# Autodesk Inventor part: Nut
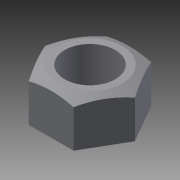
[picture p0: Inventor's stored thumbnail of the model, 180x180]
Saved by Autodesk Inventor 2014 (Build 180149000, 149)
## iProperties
Created: 2004-07
Part Number: Nut
Document SubType Name: Modeling
Designer: Autodesk, Inc.
Manufacturer: Standard
Standards Organization: Custom
Density: 1 g/cm^3
Mass: 3.54479 g
Surface Area: 21.3114 cm^2
Volume: 3.54479 cm^3
Material: Generic
Appearance: Default
Author: Autodesk, Inc.
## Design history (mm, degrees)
sketch "Sketch1"
  geometry: L1 (-13.279, 0)-(-6.64, 11.5); L2 (-6.64, 11.5)-(6.64, 11.5); L3 (6.64, 11.5)-(13.279, 0); L4 (13.279, 0)-(6.64, -11.5); L5 (6.64, -11.5)-(-6.64, -11.5); L6 (-6.64, -11.5)-(-13.279, 0); 2 further points
  constraints: 12 end point, 1 coincident, 11 other
  dimensions: "d0" = 23 distance between parallel lines of L2 L5
extrude "Extrusion1" new body sketch "Sketch1" distance "d1" = 13; taper "d2" = 0 deg
sketch "Sketch2"
  geometry: L1 (0, -2.8)-(0, 16.8) reference; L2 (13.6, 14)-(13.6, 11); L3 (13.6, 11)-(7.6, 14); L4 (7.6, 14)-(13.6, 14); L5 (13.279, 0)-(6.64, 0) reference; L6 (6.64, 0)-(-6.64, 0) reference; L7 (-6.64, 0)-(-13.279, 0) reference; L8 (-13.279, 0)-(-6.64, 0) reference; L9 (-6.64, 0)-(6.64, 0) reference; L10 (6.64, 0)-(13.279, 0) reference
  constraints: 6 end point, 1 parallel, 1 perpendicular
  dimensions: "d3" = 27.2 diameter of L2 L1; "d4" = 6 distance of L3.end L2.start; "d5" = 3 distance of L2.start L2.end; "d6" = 14 distance between parallel lines of L4 L5
revolve "Revolution1" sketch "Sketch2" stored, may be unused: angle "d7" = 90 deg
sketch "Sketch3"
  geometry: C1 r 7.5 at (0, 0); 1 further point
  constraints: 1 centre point, 1 coincident
  dimensions: "d8" = 15 diameter of C1
extrude "Extrusion2" cut sketch "Sketch3" stored distance "d9" = 13; taper "d10" = 0 deg
body "Solid1"
node "Projected Loop1"
